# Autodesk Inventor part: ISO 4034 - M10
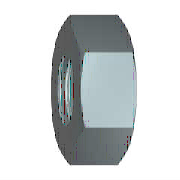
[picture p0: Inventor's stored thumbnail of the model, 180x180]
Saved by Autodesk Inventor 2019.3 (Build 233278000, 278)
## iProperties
Created: 2018-01
Part Number: ISO 4034 - M10
Material: Ocel
Description: Šestihranné matice. Výrobní řada C
Document SubType Name: Modeling
Standard: ISO 4034
Designer: B-hon
Standards Organization: CSN
Language: cs-CZ
Size Designation: M10
Categories: <MemberInstance><Categories><Category DisplayName="Spojovací materiál" InternalName="e4da775c-781d-43d5-af7c-5136215cf5a6" Mnemonic="FSTN"><Category DisplayName
Density: 7.85 g/cm^3
Appearance: Plech
IsCustomPart: 0
Author: B-hon
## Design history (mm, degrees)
sketch "Náčrt1"
  geometry: L1 (-9.238, 0)-(-4.619, 8); L2 (-4.619, 8)-(4.619, 8); L3 (4.619, 8)-(9.238, 0); L4 (9.238, 0)-(4.619, -8); L5 (4.619, -8)-(-4.619, -8); L6 (-4.619, -8)-(-9.238, 0); 2 further points
  constraints: 12 end point, 1 coincident, 1 horizontal, 11 other
  dimensions: "d0" = 18.47521 distance of L3.end L1.start (= 1.1547 x SW)
extrude "Těleso" new body sketch "Náčrt1" distance "d1" = 9.5 (= KOH); taper "d2" = 0 deg
sketch "Náčrt2"
  geometry: L1 (0, 4.619)-(0, 9.238) reference; L2 (0, 9.238)-(9.5, 9.238) reference; L3 (9.5, 4.619)-(9.5, 9.238) reference; L4 (-1.9, 0)-(11.4, 0) reference; L5 (0.715, 9.238)-(0, 8); L6 (8.785, 9.238)-(9.5, 8)
  constraints: 4 end point, 4 point on line
  dimensions: "d3" = 30 deg angle of L1 L5 (= ANG1); "d4" = 30 deg angle of L3 L6 (= ANG2); "d5" = 16 diameter of L5.end L4 (= SW0); "d6" = 16 diameter of L6.end L4 (= SW01)
revolve "Zkosení1" sketch "Náčrt2" stored, may be unused: angle "d7" = 90 deg
sketch "Náčrt3"
  geometry: A1 r 8 centre (0, 0) between (-4, -6.928) and (4, -6.928) reference; 1 further point
  constraints: 1 coincident
hole "Závit" sketch "Náčrt3" at (0, 0) diameter "d25" = 8.376; stored, may be unused: countersink angle "d29" = 82 deg, drill point angle "d31" = 118 deg; dims "d26" = 6, "d27" = 4, "d28" = 2, "d30" = 8
workaxis "Work Axis1"
workplane "Work Plane1"
body "Solid1"
chamfer "Zkosení2" distance "d8" = 0.8119 (= -0.5 x GD1 + 0.5 x NND); stored, may be unused: angle "d9" = 30 deg, second distance "d40" = 0.8119 (= -0.5 x GD1 + 0.5 x NND)
chamfer "Zkosení3" distance "d10" = 0.8119 (= -0.5 x GD1 + 0.5 x NND); stored, may be unused: angle "d11" = 30 deg, second distance "d41" = 0.8119 (= -0.5 x GD1 + 0.5 x NND)
other parameters: "ANG1" = 30 deg [user parameter; used in 1 equation term], "ANG2" = 30 deg [user parameter; used in 1 equation term], "KOH" = 9.5 [user parameter; used in 1 equation term], "SW" = 16 [user parameter; used in 4 equation terms], "SW0" = 16 (= SW) [user parameter; used in 1 equation term], "SW01" = 16 (= SW) [user parameter; used in 1 equation term], "GD1" = 8.3762 (computed from THREADDIA, PTC, TOA) [user parameter; used in 4 equation terms], "d13" = 0, "d14" = 0, "d39" = 0, "d42" = 0, "GUL" = 0.8119 (= 0.541266 x PTC) [user parameter], "TPU" = 6.66667 (computed from PTC) [user parameter], "TOA" = 30 deg [user parameter; used in 1 equation term], "PTC" = 1.5 [user parameter; used in 4 equation terms], "E0" = 18.48 (= 1.155 x SW) [user parameter], "GAL" = 0.8119 (= 0.541266 x PTC) [user parameter]
